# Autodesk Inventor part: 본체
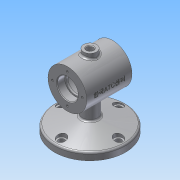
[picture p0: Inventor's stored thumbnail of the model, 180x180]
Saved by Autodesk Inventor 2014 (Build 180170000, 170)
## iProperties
Created: 2018-12
Part Number: 본체
Material: 알루미늄 6061
Document SubType Name: Modeling
Designer: sda
Density: 2.71 g/cm^3
Appearance: 알루미늄 - 평지
Mass: 687.626 g
Surface Area: 555.482 cm^2
Volume: 253.737 cm^3
Author: sda
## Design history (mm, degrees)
sketch "스케치1"
  geometry: L1 (-35, 0)-(-35, 30); L2 (-35, 30)-(35, 30); L3 (35, 30)-(35, 0); L4 (35, 0)-(-35, 0); 2 further points
  constraints: 8 end point, 2 perpendicular, 1 midpoint, 1 parallel, 1 vertical, 1 vertical alignment
  dimensions: "d0" = 60 diameter of L2 L4; "d1" = 70 distance between parallel lines of L3 L1
revolve "회전1" sketch "스케치1" stored, may be unused: angle "d2" = 90 deg
node "작업 평면1"
sketch "스케치2"
  geometry: C1 r 55 at (0, 0); 1 further point
  constraints: 1 centre point, 1 coincident
  dimensions: "d4" = 110 diameter of C1
extrude "돌출1" join sketch "스케치2" distance "d5" = 11; taper "d6" = 0 deg
sketch "스케치4"
  geometry: C1 r 55 at (0, 0) reference; C2 r 12 at (0, 0)
  constraints: 1 centre point, 1 coincident
  dimensions: "d7" = 24 diameter of C2
extrude "돌출2" join sketch "스케치4" stored distance "d8" = 11; taper "d9" = 0 deg
sketch "스케치5"
  geometry: L1 (-35, 30)-(35, 30) reference; L2 (35, 30)-(35, -30) reference; L3 (35, -30)-(12, -30) reference; L4 (12, -30)-(12, -64) reference; L5 (12, -64)-(55, -64) reference; L6 (55, -64)-(55, -75) reference; L7 (55, -75)-(-55, -75) reference; L8 (-55, -75)-(-55, -64) reference; L9 (-55, -64)-(-12, -64) reference; L10 (-12, -64)-(-12, -30) reference; L11 (-12, -30)-(-35, -30) reference; L12 (-35, -30)-(-35, 30) reference; L13 (-55, -64)-(0, -49.263); L14 (0, -49.263)-(0, -64); L15 (0, -64)-(-55, -64); 1 further point
  constraints: 6 end point, 1 collinear, 1 parallel, 1 point on line
  dimensions: "d10" = 75 deg angle of L8 L13
revolve "회전2" sketch "스케치5" stored, may be unused: angle "d11" = 90 deg
fillet "모깎기1" dims "d12" = 3
node "작업 평면2"
sketch "스케치6"
  geometry: C1 r 10 at (0, 0); 1 further point
  constraints: 1 centre point, 1 coincident
  dimensions: "d14" = 20 diameter of C1
extrude "돌출3" join sketch "스케치6" stored distance "d15" = 11; taper "d16" = 0 deg
sketch "스케치7"
  geometry: L1 (-52.776, -63.404)-(-12, -52.478) reference; L2 (-12, -52.478)-(-12, -30) reference; L3 (-12, -30)-(-35, -30) reference; L4 (-35, -30)-(-35, 30) reference; L5 (-35, 30)-(-10, 30) reference; L6 (-10, 30)-(-10, 37) reference; L7 (-10, 37)-(10, 37) reference; L8 (10, 37)-(10, 30) reference; L9 (10, 30)-(35, 30) reference; L10 (35, 30)-(35, -30) reference; L11 (35, -30)-(12, -30) reference; L12 (12, -30)-(12, -52.478) reference; L13 (12, -52.478)-(52.776, -63.404) reference; L14 (55, -66.302)-(55, -75) reference; L15 (55, -75)-(-55, -75) reference; L16 (-55, -75)-(-55, -66.302) reference; L17 (-35, 0)-(35, 0); L18 (-35, 0)-(-35, 16); L19 (-35, 16)-(-23, 16); L20 (-23, 16)-(-23, 14); L21 (-23, 14)-(-20, 14); L22 (-20, 14)-(-20, 25); L23 (-20, 25)-(20, 25); L24 (20, 25)-(20, 14); L25 (20, 14)-(23, 14); L26 (23, 14)-(23, 16); L27 (23, 16)-(35, 16); L28 (35, 16)-(35, 0); A1 r 3 centre (-52, -66.302) between (-52.776, -63.404) and (-55, -66.302) reference; A2 r 3 centre (52, -66.302) between (55, -66.302) and (52.776, -63.404) reference; 3 further points
  constraints: 24 end point, 6 parallel, 4 midpoint, 2 collinear, 2 perpendicular, 2 point on line, 1 vertical alignment
  dimensions: "d17" = 12 distance of L18.end L19.end; "d18" = 12 distance of L26.end L27.end; "d19" = 32 diameter of L19 L17; "d20" = 32 diameter of L27 L17; "d21" = 50 diameter of L23 L17; "d22" = 40 distance of L22.end L23.end; "d24" = 28 diameter of L21 L17; "d25" = 28 diameter of L25 L17
revolve "회전3" sketch "스케치7" stored, may be unused: angle "d26" = 90 deg
fillet "모깎기2" dims "d27" = 3
fillet "모깎기3" dims "d28" = 0.3
sketch "스케치8" dims "d29" = 46
  geometry: C1 r 30 at (0, 0) reference; 2 further points
  constraints: 2 horizontal alignment, 1 coincident, 2 other
hole "구멍1" sketch "스케치8" at (23, 0) diameter "d30" = 3.242; stored, may be unused: countersink angle "d34" = 90 deg, drill point angle "d36" = 118 deg; dims "d31" = 8, "d32" = 4, "d33" = 2, "d35" = 10
chamfer "모따기1" distance "d40" = 1; stored, may be unused: second distance "d41" = 2, angle "d42" = 45 deg
hole "구멍2" diameter "d45" = 10; stored, may be unused: countersink angle "d49" = 90 deg, drill point angle "d51" = 118 deg; dims "d43" = 10, "d44" = 10, "d46" = 8, "d47" = 4, "d48" = 2, "d50" = 10
chamfer "모따기2" distance "d52" = 1; stored, may be unused: second distance "d53" = 2, angle "d54" = 45 deg
sketch "스케치9" dims "d55" = 88
  geometry: C1 r 55 at (0, 0) reference; 2 further points
  constraints: 2 vertical alignment, 1 coincident, 2 other
hole "구멍3" sketch "스케치9" at (0, 44) diameter "d56" = 9; stored, may be unused: countersink angle "d60" = 90 deg, drill point angle "d62" = 0 deg; dims "d57" = 8, "d58" = 4, "d59" = 2, "d61" = 20
node "작업 평면3"
sketch "스케치10"
  geometry: C1 r 4.5 at (0, 44) reference; C2 r 54.703 at (0, 0) reference; C3 r 7 at (0, 44); 1 further point
  constraints: 1 centre point, 1 coincident
  dimensions: "d64" = 14 diameter of C3
extrude "돌출4" cut sketch "스케치10" distance "d65" = 11; taper "d66" = 0 deg
fillet "모깎기4" dims "d70" = 3
fillet "모깎기5" dims "d71" = 3
node "작업 평면4"
sketch "스케치12"
  geometry: L1 (35, 30)-(-35, 30) reference; L2 (-10, 37)-(10, 37) reference; L3 (-35, 30)-(-35, -30) reference; 2 further points
  constraints: 1 other
  dimensions: "d73" = 35 distance from line of L3 point (0, 0); "d74" = 30 distance from line of L1 point (0, 0)
feature "엠보싱1" sketch "스케치12" dims "d75" = 0.5, "d76" = 0
node "솔리드1"
pattern_circular "원형 패턴1" dims angle "d38" = 360 deg
mirror "대칭1"
pattern_circular "원형 패턴2" dims angle "d68" = 360 deg
node "절단 모서리 투영2"
node "절단 모서리 투영3"
node "절단 모서리 투영4"
other parameters: "d3" = -75, "d13" = -112
